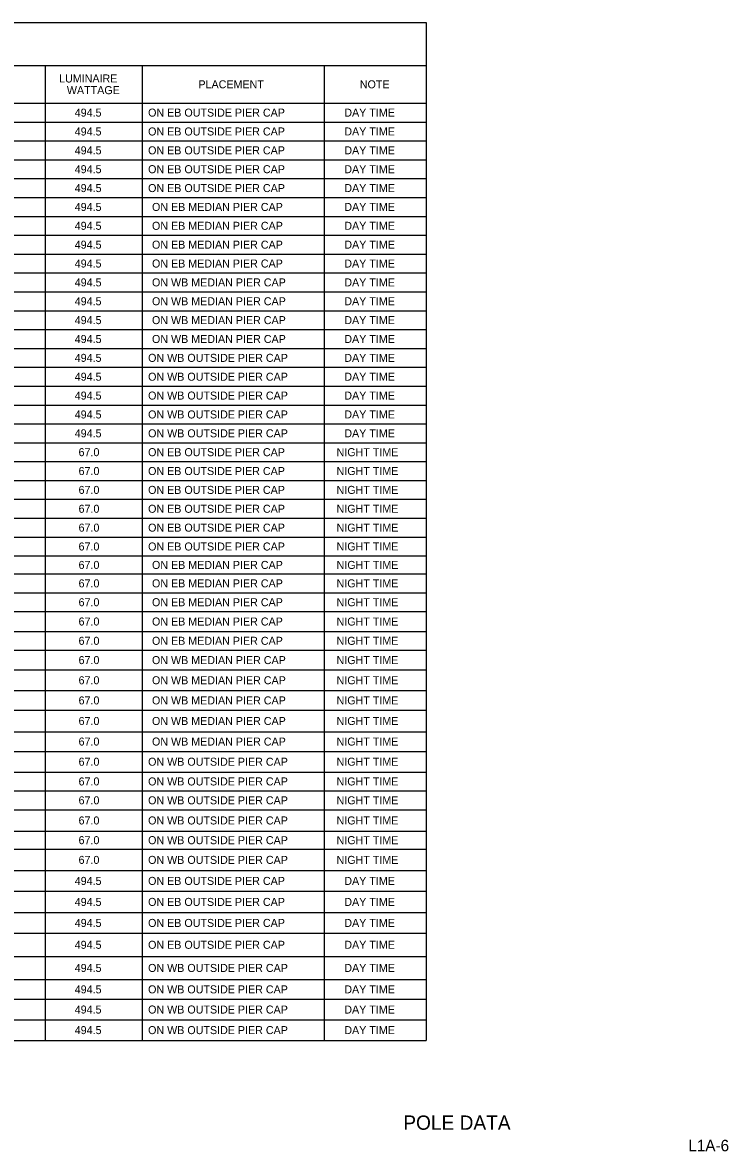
# Model space of a CAD drawing. Extents: x -816.7 to -727.6, y -2197.9 to -2187.8.
# Drawn here: x -770.86 to -764.69, y -2197.65 to -2187.77 of the extents above; entities that cross this region are included whole.
import ezdxf

# ---------------------------------------------------------------- set-up
doc = ezdxf.new("R2010")
doc.units = 0
for name, color, linetype in [('ClipBorder_dp', 7, 'Continuous'), ('MatchLines_dp', 7, 'Continuous'), ('NorthArw_dp', 7, 'Continuous'), ('Scale_dp', 7, 'Continuous'), ('SignWorkZone', 7, 'Continuous'), ('TextLabel', 7, 'Continuous')]:
    doc.layers.add(name, color=color, linetype=linetype)

msp = doc.modelspace()

# ---------------------------------------------------------------- linework, layer by layer
at = {"layer": 'MatchLines_dp'}
for p, q in [((-777.0968, -2188.4786), (-767.3318, -2188.4786)), ((-777.0968, -2188.6436), (-767.3318, -2188.6436)), ((-777.0968, -2188.6436), (-767.3318, -2188.6436)), ((-777.0968, -2188.8086), (-767.3318, -2188.8086)), ((-777.0968, -2188.8086), (-767.3318, -2188.8086)), ((-777.0968, -2188.9736), (-767.3318, -2188.9736)), ((-777.0968, -2188.9736), (-767.3318, -2188.9736)), ((-777.0968, -2189.1386), (-767.3318, -2189.1386)), ((-777.0968, -2189.1386), (-767.3318, -2189.1386)), ((-777.0968, -2189.3036), (-767.3318, -2189.3036)), ((-777.0968, -2189.3036), (-767.3318, -2189.3036)), ((-777.0968, -2189.4686), (-767.3318, -2189.4686)), ((-774.2768, -2189.4686), (-767.3318, -2189.4686)), ((-777.0968, -2189.6336), (-767.3318, -2189.6336)), ((-777.0968, -2189.6336), (-767.3318, -2189.6336)), ((-777.0968, -2189.7986), (-767.3318, -2189.7986)), ((-777.0968, -2189.7986), (-767.3318, -2189.7986)), ((-777.0968, -2189.9636), (-767.3318, -2189.9636)), ((-777.0968, -2189.9636), (-767.3318, -2189.9636)), ((-777.0968, -2190.1286), (-767.3318, -2190.1286)), ((-777.0968, -2190.1286), (-767.3318, -2190.1286)), ((-777.0968, -2190.2936), (-767.3318, -2190.2936)), ((-777.0968, -2190.2936), (-767.3318, -2190.2936)), ((-777.0968, -2190.4586), (-767.3318, -2190.4586)), ((-777.0968, -2190.4586), (-767.3318, -2190.4586)), ((-777.0968, -2190.6236), (-767.3318, -2190.6236)), ((-777.0968, -2190.6236), (-767.3318, -2190.6236)), ((-777.0968, -2190.7886), (-767.3318, -2190.7886)), ((-777.0968, -2190.7886), (-767.3318, -2190.7886)), ((-777.0968, -2190.9536), (-767.3318, -2190.9536)), ((-777.0968, -2190.9536), (-767.3318, -2190.9536)), ((-777.0968, -2191.1186), (-767.3318, -2191.1186)), ((-777.0968, -2191.1186), (-767.3318, -2191.1186)), ((-777.0968, -2191.2836), (-767.3318, -2191.2836)), ((-777.0968, -2191.2836), (-767.3318, -2191.2836)), ((-777.0968, -2191.4486), (-767.3318, -2191.4486)), ((-777.0968, -2191.4486), (-767.3318, -2191.4486)), ((-777.0968, -2191.6136), (-767.3318, -2191.6136)), ((-777.0968, -2191.6136), (-767.3318, -2191.6136)), ((-777.0968, -2191.7786), (-767.3318, -2191.7786)), ((-777.0968, -2191.7786), (-767.3318, -2191.7786)), ((-777.0968, -2191.9436), (-767.3318, -2191.9436)), ((-777.0968, -2191.9436), (-767.3318, -2191.9436)), ((-777.0968, -2192.1086), (-767.3318, -2192.1086)), ((-777.0968, -2192.1086), (-767.3318, -2192.1086)), ((-777.0968, -2192.2736), (-767.3318, -2192.2736)), ((-777.0968, -2192.2736), (-767.3318, -2192.2736)), ((-777.0968, -2192.4386), (-767.3318, -2192.4386)), ((-777.0968, -2192.4386), (-767.3318, -2192.4386)), ((-777.0968, -2192.5961), (-767.3318, -2192.5961)), ((-777.0968, -2192.5961), (-767.3318, -2192.5961)), ((-777.0968, -2192.7611), (-767.3318, -2192.7611)), ((-777.0968, -2192.7611), (-767.3318, -2192.7611)), ((-777.0968, -2192.9261), (-767.3318, -2192.9261)), ((-777.0968, -2192.9261), (-767.3318, -2192.9261)), ((-777.0968, -2193.0986), (-767.3318, -2193.0986)), ((-777.0968, -2193.0986), (-767.3318, -2193.0986)), ((-777.0968, -2193.2636), (-767.3318, -2193.2636)), ((-777.0968, -2193.2636), (-767.3318, -2193.2636)), ((-777.0968, -2193.4361), (-767.3318, -2193.4361)), ((-777.0968, -2193.4361), (-767.3318, -2193.4361)), ((-777.0968, -2193.6161), (-767.3318, -2193.6161)), ((-777.0968, -2193.6161), (-767.3318, -2193.6161)), ((-777.0968, -2193.7886), (-767.3318, -2193.7886)), ((-777.0968, -2193.7886), (-767.3318, -2193.7886)), ((-777.0968, -2193.9761), (-767.3318, -2193.9761)), ((-777.0968, -2193.9761), (-767.3318, -2193.9761)), ((-777.0968, -2194.1486), (-767.3318, -2194.1486)), ((-777.0968, -2194.1486), (-767.3318, -2194.1486)), ((-777.0968, -2194.3286), (-767.3318, -2194.3286)), ((-777.0968, -2194.3286), (-767.3318, -2194.3286)), ((-777.0968, -2194.4936), (-767.3318, -2194.4936)), ((-777.0968, -2194.4936), (-767.3318, -2194.4936)), ((-777.0968, -2194.6586), (-767.3318, -2194.6586)), ((-777.0968, -2194.6586), (-767.3318, -2194.6586)), ((-777.0968, -2194.8461), (-767.3318, -2194.8461)), ((-777.0968, -2194.8461), (-767.3318, -2194.8461)), ((-777.0968, -2195.0036), (-767.3318, -2195.0036)), ((-777.0968, -2195.0036), (-767.3318, -2195.0036)), ((-777.0968, -2195.1911), (-767.3318, -2195.1911)), ((-777.0968, -2195.1911), (-767.3318, -2195.1911)), ((-777.0968, -2195.3711), (-767.3318, -2195.3711)), ((-777.0968, -2195.3711), (-767.3318, -2195.3711)), ((-777.0968, -2195.5586), (-767.3318, -2195.5586)), ((-777.0968, -2195.5586), (-767.3318, -2195.5586)), ((-777.0968, -2195.7386), (-767.3318, -2195.7386)), ((-777.0968, -2195.7386), (-767.3318, -2195.7386)), ((-777.0968, -2195.9411), (-767.3318, -2195.9411)), ((-777.0968, -2195.9411), (-767.3318, -2195.9411)), ((-777.0968, -2196.1436), (-767.3318, -2196.1436)), ((-777.0968, -2196.1436), (-767.3318, -2196.1436)), ((-777.0968, -2196.3161), (-767.3318, -2196.3161)), ((-777.0968, -2196.3161), (-767.3318, -2196.3161)), ((-777.0968, -2196.4961), (-767.3318, -2196.4961)), ((-777.0968, -2196.4961), (-767.3318, -2196.4961))]:
    msp.add_line(p, q, dxfattribs=at)
at = {"layer": 'NorthArw_dp'}
for p, q in [((-777.0968, -2187.7736), (-767.3318, -2187.7736)), ((-767.3318, -2187.7736), (-767.3318, -2196.6761)), ((-777.0968, -2188.1486), (-767.3318, -2188.1486)), ((-777.0968, -2188.1486), (-767.3318, -2188.1486)), ((-768.2243, -2188.1486), (-768.2243, -2196.6761)), ((-768.2243, -2188.4786), (-768.2243, -2196.6761)), ((-777.0968, -2196.6761), (-767.3318, -2196.6761))]:
    msp.add_line(p, q, dxfattribs=at)
at = {"layer": 'Scale_dp'}
for p, q in [((-770.6618, -2188.1486), (-770.6618, -2196.6761)), ((-770.6618, -2188.1486), (-770.6618, -2196.6761)), ((-769.8143, -2188.1486), (-769.8143, -2196.6761)), ((-769.8143, -2188.1486), (-769.8143, -2196.6761)), ((-768.2243, -2188.1486), (-768.2243, -2188.4786)), ((-777.0968, -2188.4786), (-767.3318, -2188.4786))]:
    msp.add_line(p, q, dxfattribs=at)

# ---------------------------------------------------------------- texts
at = {"layer": 'ClipBorder_dp'}
for s, p in [('LUMINAIRE', (-770.5407, -2188.2976)), ('PLACEMENT', (-769.3224, -2188.3486)), ('NOTE', (-767.9114, -2188.3486)), ('WATTAGE', (-770.473, -2188.3996)), ('494.5', (-770.4041, -2188.5961)), ('ON EB OUTSIDE PIER CAP', (-769.7625, -2188.5961)), ('DAY TIME', (-768.0469, -2188.5961)), ('494.5', (-770.4041, -2188.7611)), ('ON EB OUTSIDE PIER CAP', (-769.7625, -2188.7611)), ('DAY TIME', (-768.0469, -2188.7611)), ('494.5', (-770.4041, -2188.9261)), ('ON EB OUTSIDE PIER CAP', (-769.7625, -2188.9261)), ('DAY TIME', (-768.0469, -2188.9261)), ('494.5', (-770.4041, -2189.0911)), ('ON EB OUTSIDE PIER CAP', (-769.7625, -2189.0911)), ('DAY TIME', (-768.0469, -2189.0911)), ('494.5', (-770.4041, -2189.2561)), ('ON EB OUTSIDE PIER CAP', (-769.7625, -2189.2561)), ('DAY TIME', (-768.0469, -2189.2561)), ('494.5', (-770.4041, -2189.4211)), ('ON EB MEDIAN PIER CAP', (-769.7286, -2189.4211)), ('DAY TIME', (-768.0469, -2189.4211)), ('494.5', (-770.4041, -2189.5861)), ('ON EB MEDIAN PIER CAP', (-769.7286, -2189.5861)), ('DAY TIME', (-768.0469, -2189.5861)), ('494.5', (-770.4041, -2189.7511)), ('ON EB MEDIAN PIER CAP', (-769.7286, -2189.7511)), ('DAY TIME', (-768.0469, -2189.7511)), ('494.5', (-770.4041, -2189.9161)), ('ON EB MEDIAN PIER CAP', (-769.7286, -2189.9161)), ('DAY TIME', (-768.0469, -2189.9161)), ('494.5', (-770.4041, -2190.0811)), ('ON WB MEDIAN PIER CAP', (-769.7286, -2190.0811)), ('DAY TIME', (-768.0469, -2190.0811)), ('494.5', (-770.4041, -2190.2461)), ('ON WB MEDIAN PIER CAP', (-769.7286, -2190.2461)), ('DAY TIME', (-768.0469, -2190.2461)), ('494.5', (-770.4041, -2190.4111)), ('ON WB MEDIAN PIER CAP', (-769.7286, -2190.4111)), ('DAY TIME', (-768.0469, -2190.4111)), ('494.5', (-770.4041, -2190.5761)), ('ON WB MEDIAN PIER CAP', (-769.7286, -2190.5761)), ('DAY TIME', (-768.0469, -2190.5761)), ('494.5', (-770.4041, -2190.7411)), ('ON WB OUTSIDE PIER CAP', (-769.7625, -2190.7411)), ('DAY TIME', (-768.0469, -2190.7411)), ('494.5', (-770.4041, -2190.9061)), ('ON WB OUTSIDE PIER CAP', (-769.7625, -2190.9061)), ('DAY TIME', (-768.0469, -2190.9061)), ('494.5', (-770.4041, -2191.0711)), ('ON WB OUTSIDE PIER CAP', (-769.7625, -2191.0711)), ('DAY TIME', (-768.0469, -2191.0711)), ('494.5', (-770.4041, -2191.2361)), ('ON WB OUTSIDE PIER CAP', (-769.7625, -2191.2361)), ('DAY TIME', (-768.0469, -2191.2361)), ('494.5', (-770.4041, -2191.4011)), ('ON WB OUTSIDE PIER CAP', (-769.7625, -2191.4011)), ('DAY TIME', (-768.0469, -2191.4011)), ('67.0', (-770.3705, -2191.5661)), ('ON EB OUTSIDE PIER CAP', (-769.7625, -2191.5661)), ('NIGHT TIME', (-768.1146, -2191.5661)), ('67.0', (-770.3705, -2191.7311)), ('ON EB OUTSIDE PIER CAP', (-769.7625, -2191.7311)), ('NIGHT TIME', (-768.1146, -2191.7311)), ('67.0', (-770.3705, -2191.8961)), ('ON EB OUTSIDE PIER CAP', (-769.7625, -2191.8961)), ('NIGHT TIME', (-768.1146, -2191.8961)), ('67.0', (-770.3705, -2192.0611)), ('ON EB OUTSIDE PIER CAP', (-769.7625, -2192.0611)), ('NIGHT TIME', (-768.1146, -2192.0611)), ('67.0', (-770.3705, -2192.2261)), ('ON EB OUTSIDE PIER CAP', (-769.7625, -2192.2261)), ('NIGHT TIME', (-768.1146, -2192.2261)), ('67.0', (-770.3705, -2192.3911)), ('ON EB OUTSIDE PIER CAP', (-769.7625, -2192.3911)), ('NIGHT TIME', (-768.1146, -2192.3911)), ('67.0', (-770.3705, -2192.5523)), ('ON EB MEDIAN PIER CAP', (-769.7286, -2192.5523)), ('NIGHT TIME', (-768.1146, -2192.5523)), ('67.0', (-770.3705, -2192.7136)), ('ON EB MEDIAN PIER CAP', (-769.7286, -2192.7136)), ('NIGHT TIME', (-768.1146, -2192.7136)), ('67.0', (-770.3705, -2192.8786)), ('ON EB MEDIAN PIER CAP', (-769.7286, -2192.8786)), ('NIGHT TIME', (-768.1146, -2192.8786)), ('67.0', (-770.3705, -2193.0473)), ('ON EB MEDIAN PIER CAP', (-769.7286, -2193.0473)), ('NIGHT TIME', (-768.1146, -2193.0473)), ('67.0', (-770.3705, -2193.2161)), ('ON EB MEDIAN PIER CAP', (-769.7286, -2193.2161)), ('NIGHT TIME', (-768.1146, -2193.2161)), ('67.0', (-770.3705, -2193.3848)), ('ON WB MEDIAN PIER CAP', (-769.7286, -2193.3848)), ('NIGHT TIME', (-768.1146, -2193.3848)), ('67.0', (-770.3705, -2193.5611)), ('ON WB MEDIAN PIER CAP', (-769.7286, -2193.5611)), ('NIGHT TIME', (-768.1146, -2193.5611)), ('67.0', (-770.3705, -2193.7373)), ('ON WB MEDIAN PIER CAP', (-769.7286, -2193.7373)), ('NIGHT TIME', (-768.1146, -2193.7373)), ('67.0', (-770.3705, -2193.9173)), ('ON WB MEDIAN PIER CAP', (-769.7286, -2193.9173)), ('NIGHT TIME', (-768.1146, -2193.9173)), ('67.0', (-770.3705, -2194.0973)), ('ON WB MEDIAN PIER CAP', (-769.7286, -2194.0973)), ('NIGHT TIME', (-768.1146, -2194.0973)), ('67.0', (-770.3705, -2194.2736)), ('ON WB OUTSIDE PIER CAP', (-769.7625, -2194.2736)), ('NIGHT TIME', (-768.1146, -2194.2736)), ('67.0', (-770.3705, -2194.4461)), ('ON WB OUTSIDE PIER CAP', (-769.7625, -2194.4461)), ('NIGHT TIME', (-768.1146, -2194.4461)), ('67.0', (-770.3705, -2194.6111)), ('ON WB OUTSIDE PIER CAP', (-769.7625, -2194.6111)), ('NIGHT TIME', (-768.1146, -2194.6111)), ('67.0', (-770.3705, -2194.7873)), ('ON WB OUTSIDE PIER CAP', (-769.7625, -2194.7873)), ('NIGHT TIME', (-768.1146, -2194.7873)), ('67.0', (-770.3705, -2194.9598)), ('ON WB OUTSIDE PIER CAP', (-769.7625, -2194.9598)), ('NIGHT TIME', (-768.1146, -2194.9598)), ('67.0', (-770.3705, -2195.1323)), ('ON WB OUTSIDE PIER CAP', (-769.7625, -2195.1323)), ('NIGHT TIME', (-768.1146, -2195.1323)), ('494.5', (-770.4041, -2195.3161)), ('ON EB OUTSIDE PIER CAP', (-769.7625, -2195.3161)), ('DAY TIME', (-768.0469, -2195.3161)), ('494.5', (-770.4041, -2195.4998)), ('ON EB OUTSIDE PIER CAP', (-769.7625, -2195.4998)), ('DAY TIME', (-768.0469, -2195.4998)), ('494.5', (-770.4041, -2195.6836)), ('ON EB OUTSIDE PIER CAP', (-769.7625, -2195.6836)), ('DAY TIME', (-768.0469, -2195.6836)), ('494.5', (-770.4041, -2195.8748)), ('ON EB OUTSIDE PIER CAP', (-769.7625, -2195.8748)), ('DAY TIME', (-768.0469, -2195.8748)), ('494.5', (-770.4041, -2196.0773)), ('ON WB OUTSIDE PIER CAP', (-769.7625, -2196.0773)), ('DAY TIME', (-768.0469, -2196.0773)), ('494.5', (-770.4041, -2196.2648)), ('ON WB OUTSIDE PIER CAP', (-769.7625, -2196.2648)), ('DAY TIME', (-768.0469, -2196.2648)), ('494.5', (-770.4041, -2196.4411)), ('ON WB OUTSIDE PIER CAP', (-769.7625, -2196.4411)), ('DAY TIME', (-768.0469, -2196.4411)), ('494.5', (-770.4041, -2196.6211)), ('ON WB OUTSIDE PIER CAP', (-769.7625, -2196.6211)), ('DAY TIME', (-768.0469, -2196.6211))]:
    msp.add_text(s, height=0.07, dxfattribs=at).set_placement(p)
at = {"layer": 'SignWorkZone'}
msp.add_text('L1A-6 ', height=0.1, dxfattribs=at).set_placement((-765.0393, -2197.6458))
at = {"layer": 'TextLabel'}
msp.add_text('POLE DATA', height=0.125, dxfattribs=at).set_placement((-767.5312, -2197.4577))

doc.saveas('drawing.dxf')
